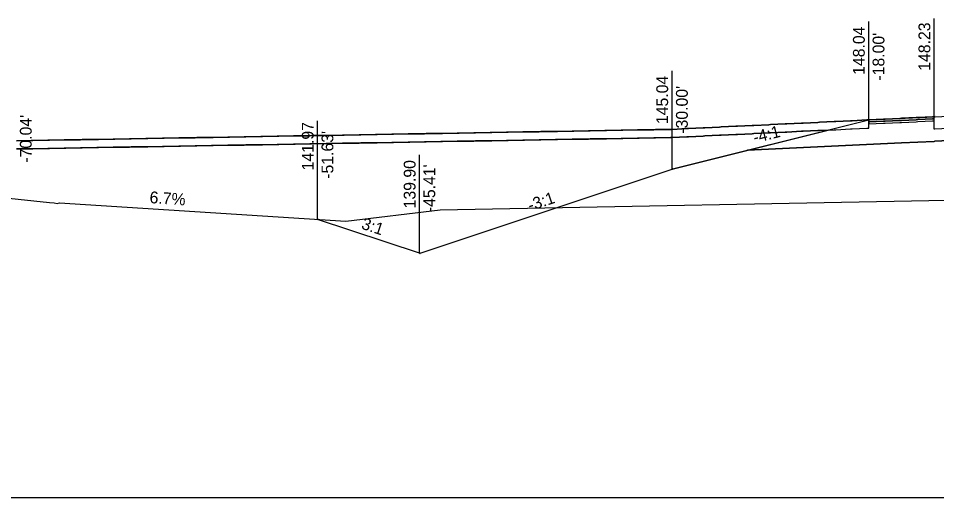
# Model space of a CAD drawing. Extents: x -26 to 4403, y -13 to 9578.
# Drawn here: x 1180.1 to 1236.1, y 1000 to 1029.2 of the extents above; entities that cross this region are included whole.
import ezdxf

# ---------------------------------------------------------------- set-up
doc = ezdxf.new("R2010")
doc.units = 0
for name, color, linetype in [('_CIVIL_CONSTRUCTION', 7, 'Continuous'), ('CONST_DCH', 7, 'Continuous'), ('CONST_LV3', 7, 'Continuous'), ('DTM_CORRIDOR', 7, 'Continuous'), ('DTM_P_FINISHED_GRADE', 7, 'Continuous'), ('DTM_TEMP_DROP', 7, 'Continuous'), ('DTM_X_GROUND', 7, 'Continuous'), ('SLOPE_STAKES_FILL', 7, 'Continuous'), ('XS_CELL', 7, 'Continuous'), ('XS_M_SHAPES_EARTHWORK', 7, 'Continuous'), ('XS_P_ASPHALT', 7, 'Continuous'), ('XS_P_DR_ASPHALT', 7, 'Continuous'), ('XS_P_DR_ASPHALT_B', 7, 'Continuous'), ('XS_P_DR_GRAVEL', 7, 'Continuous'), ('XS_P_GROUND', 7, 'Continuous'), ('XS_P_SHOULDER', 7, 'Continuous'), ('XS_P_SUBGRADE_GRANULAR', 7, 'Continuous'), ('XS_P_TX_CLEARZONE', 7, 'Continuous'), ('XS_P_TX_FS_BS', 7, 'Continuous')]:
    doc.layers.add(name, color=color, linetype=linetype)

msp = doc.modelspace()

# ---------------------------------------------------------------- linework, layer by layer
at = {"layer": 'CONST_LV3'}
for points in [[(1180, 1021.763), (1180.897, 1021.779), (1181, 1021.781), (1181.897, 1021.796), (1182, 1021.798), (1182.897, 1021.814), (1183, 1021.816), (1183.897, 1021.831), (1184, 1021.833), (1184.897, 1021.849), (1185, 1021.851), (1185.897, 1021.866), (1186, 1021.868), (1186.897, 1021.884), (1187, 1021.885), (1187.897, 1021.901), (1188, 1021.903), (1188.897, 1021.918), (1189, 1021.92), (1189.897, 1021.936), (1190, 1021.938), (1190.897, 1021.953), (1191, 1021.955), (1191.897, 1021.971), (1192, 1021.973), (1192.897, 1021.988), (1193, 1021.99), (1193.897, 1022.006), (1194, 1022.007), (1194.897, 1022.023), (1195, 1022.025), (1195.897, 1022.041), (1196, 1022.042), (1196.897, 1022.058), (1197, 1022.06), (1197.897, 1022.075), (1198, 1022.077), (1198.897, 1022.093), (1199, 1022.095), (1199.897, 1022.11), (1200, 1022.112), (1200.897, 1022.128), (1201, 1022.129), (1201.897, 1022.145), (1202, 1022.147), (1202.897, 1022.163), (1203, 1022.164), (1203.897, 1022.18), (1204, 1022.182), (1204.897, 1022.197), (1205, 1022.199), (1205.897, 1022.215), (1206, 1022.217), (1206.897, 1022.232), (1207, 1022.234), (1207.897, 1022.25), (1208, 1022.252), (1208.897, 1022.267), (1209, 1022.269), (1209.897, 1022.285), (1210, 1022.286), (1210.897, 1022.302), (1211, 1022.304), (1211.897, 1022.319), (1212, 1022.321), (1212.897, 1022.337), (1213, 1022.339), (1213.897, 1022.354), (1214, 1022.356), (1214.897, 1022.372), (1215, 1022.374), (1215.897, 1022.389), (1216, 1022.391), (1216.897, 1022.407), (1217, 1022.408), (1217.897, 1022.424), (1218, 1022.426), (1218.897, 1022.441), (1219, 1022.443), (1219.897, 1022.459), (1220, 1022.461), (1220.897, 1022.504), (1221, 1022.509), (1221.897, 1022.552), (1222, 1022.557), (1222.897, 1022.6), (1223, 1022.605), (1223.897, 1022.648), (1224, 1022.653), (1224.897, 1022.696), (1225, 1022.701), (1225.897, 1022.744), (1226, 1022.749), (1226.897, 1022.792), (1227, 1022.797), (1227.897, 1022.84), (1228, 1022.845), (1228.897, 1022.888), (1229, 1022.893), (1229.897, 1022.936), (1230, 1022.941), (1230.897, 1022.984), (1231, 1022.989), (1231.897, 1023.032), (1232, 1023.037), (1232.897, 1023.08), (1233, 1023.085), (1233.897, 1023.128), (1234, 1023.133), (1234.897, 1023.176), (1235, 1023.181), (1235.897, 1023.224), (1236, 1023.229)], [(1220, 1020.037), (1220.013, 1020.04), (1224.574, 1021.18)]]:
    msp.add_lwpolyline(points, dxfattribs=at)
at = {"layer": 'DTM_P_FINISHED_GRADE'}
for points in [[(1180, 1021.763), (1180.897, 1021.779), (1181, 1021.781), (1181.897, 1021.796), (1182, 1021.798), (1182.897, 1021.814), (1183, 1021.816), (1183.897, 1021.831), (1184, 1021.833), (1184.897, 1021.849), (1185, 1021.851), (1185.897, 1021.866), (1186, 1021.868), (1186.897, 1021.884), (1187, 1021.885), (1187.897, 1021.901), (1188, 1021.903), (1188.897, 1021.918), (1189, 1021.92), (1189.897, 1021.936), (1190, 1021.938), (1190.897, 1021.953), (1191, 1021.955), (1191.897, 1021.971), (1192, 1021.973), (1192.897, 1021.988), (1193, 1021.99), (1193.897, 1022.006), (1194, 1022.007), (1194.897, 1022.023), (1195, 1022.025), (1195.897, 1022.041), (1196, 1022.042), (1196.897, 1022.058), (1197, 1022.06), (1197.897, 1022.075), (1198, 1022.077), (1198.897, 1022.093), (1199, 1022.095), (1199.897, 1022.11), (1200, 1022.112), (1200.897, 1022.128), (1201, 1022.129), (1201.897, 1022.145), (1202, 1022.147), (1202.897, 1022.163), (1203, 1022.164), (1203.897, 1022.18), (1204, 1022.182), (1204.897, 1022.197), (1205, 1022.199), (1205.897, 1022.215), (1206, 1022.217), (1206.897, 1022.232), (1207, 1022.234), (1207.897, 1022.25), (1208, 1022.252), (1208.897, 1022.267), (1209, 1022.269), (1209.897, 1022.285), (1210, 1022.286), (1210.897, 1022.302), (1211, 1022.304), (1211.897, 1022.319), (1212, 1022.321), (1212.897, 1022.337), (1213, 1022.339), (1213.897, 1022.354), (1214, 1022.356), (1214.897, 1022.372), (1215, 1022.374), (1215.897, 1022.389), (1216, 1022.391), (1216.897, 1022.407), (1217, 1022.408), (1217.897, 1022.424), (1218, 1022.426), (1218.897, 1022.441), (1219, 1022.443), (1219.897, 1022.459), (1220, 1022.461), (1220.897, 1022.504), (1221, 1022.509), (1221.897, 1022.552), (1222, 1022.557), (1222.897, 1022.6), (1223, 1022.605), (1223.897, 1022.648), (1224, 1022.653), (1224.897, 1022.696), (1225, 1022.701), (1225.897, 1022.744), (1226, 1022.749), (1226.897, 1022.792), (1227, 1022.797), (1227.897, 1022.84), (1228, 1022.845), (1228.897, 1022.888), (1229, 1022.893), (1229.897, 1022.936), (1230, 1022.941), (1230.897, 1022.984), (1231, 1022.989), (1231.897, 1023.032), (1232, 1023.037)], [(1232, 1023.037), (1232.897, 1023.08), (1233, 1023.085), (1233.897, 1023.128), (1234, 1023.133), (1234.897, 1023.176), (1235, 1023.181), (1235.897, 1023.224), (1236, 1023.229)]]:
    msp.add_lwpolyline(points, dxfattribs=at)
at = {"layer": 'DTM_X_GROUND'}
msp.add_lwpolyline([(1084.364, 1020.049), (1100.532, 1021.44), (1114.605, 1024.089), (1116.924, 1024.52), (1120.223, 1025.074), (1123.578, 1025.386), (1123.824, 1025.384), (1125.939, 1025.479), (1126.01, 1025.486), (1135.182, 1025.868), (1142.445, 1025.917), (1146.83, 1025.95), (1147.343, 1025.854), (1148.21, 1025.742), (1149.366, 1025.63), (1164.218, 1020.156), (1164.971, 1019.814), (1182.014, 1017.995), (1182.294, 1017.975), (1182.479, 1017.946), (1182.623, 1017.982), (1200.1, 1016.861), (1205.856, 1017.542), (1237.811, 1018.169)], dxfattribs=at)
at = {"layer": 'XS_CELL'}
msp.add_line((1000, 1000), (1250, 1000), dxfattribs=at)
at = {"layer": 'XS_M_SHAPES_EARTHWORK'}
for points in [[(1250, 1022.401), (1236.039, 1021.731), (1236, 1021.729), (1234.006, 1021.633), (1234, 1021.633), (1224.601, 1021.182), (1224.574, 1021.18), (1229.525, 1022.418), (1229, 1022.393), (1228.897, 1022.388), (1228, 1022.345), (1227.897, 1022.34), (1227, 1022.297), (1226.897, 1022.292), (1226, 1022.249), (1225.897, 1022.244), (1225, 1022.201), (1224.897, 1022.196), (1224, 1022.153), (1223.897, 1022.148), (1223, 1022.105), (1222.897, 1022.1), (1222, 1022.057), (1221.897, 1022.052), (1221, 1022.009), (1220.897, 1022.004), (1220, 1021.961), (1219.897, 1021.959), (1219, 1021.943), (1218.897, 1021.941), (1218, 1021.926), (1217.897, 1021.924), (1217, 1021.908), (1216.897, 1021.907), (1216, 1021.891), (1215.897, 1021.889), (1215, 1021.874), (1214.897, 1021.872), (1214, 1021.856), (1213.897, 1021.854), (1213, 1021.839), (1212.897, 1021.837), (1212, 1021.821), (1211.897, 1021.819), (1211, 1021.804), (1210.897, 1021.802), (1210, 1021.786), (1209.897, 1021.785), (1209, 1021.769), (1208.897, 1021.767), (1208, 1021.752), (1207.897, 1021.75), (1207, 1021.734), (1206.897, 1021.732), (1206, 1021.717), (1205.897, 1021.715), (1205, 1021.699), (1204.897, 1021.697), (1204, 1021.682), (1203.897, 1021.68), (1203, 1021.664), (1202.897, 1021.663), (1202, 1021.647), (1201.897, 1021.645), (1201, 1021.629), (1200.897, 1021.628), (1200, 1021.612), (1199.897, 1021.61), (1199, 1021.595), (1198.897, 1021.593), (1198, 1021.577), (1197.897, 1021.575), (1197, 1021.56), (1196.897, 1021.558), (1196, 1021.542), (1195.897, 1021.541), (1195, 1021.525), (1194.897, 1021.523), (1194, 1021.507), (1193.897, 1021.506), (1193, 1021.49), (1192.897, 1021.488), (1192, 1021.473), (1191.897, 1021.471), (1191, 1021.455), (1190.897, 1021.453), (1190, 1021.438), (1189.897, 1021.436), (1189, 1021.42), (1188.897, 1021.418), (1188, 1021.403), (1187.897, 1021.401), (1187, 1021.385), (1186.897, 1021.384), (1186, 1021.368), (1185.897, 1021.366), (1185, 1021.351), (1184.897, 1021.349), (1184, 1021.333), (1183.897, 1021.331), (1183, 1021.316), (1182.897, 1021.314), (1182, 1021.298), (1181.897, 1021.296), (1181, 1021.281), (1180.897, 1021.279), (1180, 1021.263)], [(1164.971, 1019.814), (1182.014, 1017.995), (1182.294, 1017.975), (1182.479, 1017.946), (1182.623, 1017.982), (1200.1, 1016.861), (1205.856, 1017.542), (1237.811, 1018.169)]]:
    msp.add_lwpolyline(points, dxfattribs=at)
at = {"layer": 'XS_P_ASPHALT'}
msp.add_lwpolyline([(1236.039, 1023.231), (1250, 1023.901), (1250.039, 1023.903), (1264, 1024.573), (1264, 1023.825), (1264, 1023.823), (1250.039, 1023.153), (1250, 1023.151), (1236.039, 1022.481), (1236, 1022.479), (1236, 1022.481), (1236, 1023.229), (1236.039, 1023.231)], dxfattribs=at)
at = {"layer": 'XS_P_DR_ASPHALT'}
msp.add_lwpolyline([(1232, 1023.037), (1232, 1022.912), (1232.897, 1022.955), (1232.897, 1022.955), (1233, 1022.96), (1233.897, 1023.003), (1233.897, 1023.003), (1234, 1023.008), (1234.897, 1023.051), (1235, 1023.056), (1235, 1023.056), (1235.897, 1023.099), (1236, 1023.104), (1236, 1023.229), (1235.897, 1023.224), (1235, 1023.181), (1235, 1023.181), (1234.897, 1023.176), (1234, 1023.133), (1233.897, 1023.128), (1233.897, 1023.128), (1233, 1023.085), (1232.897, 1023.08), (1232.897, 1023.08), (1232, 1023.037)], dxfattribs=at)
at = {"layer": 'XS_P_DR_ASPHALT_B'}
msp.add_lwpolyline([(1232, 1022.912), (1232, 1022.787), (1232.897, 1022.83), (1232.897, 1022.83), (1233, 1022.835), (1233.897, 1022.878), (1233.897, 1022.878), (1234, 1022.883), (1234.897, 1022.926), (1235, 1022.931), (1235, 1022.931), (1235.897, 1022.974), (1236, 1022.979), (1236, 1023.104), (1235.897, 1023.099), (1235, 1023.056), (1235, 1023.056), (1234.897, 1023.051), (1234, 1023.008), (1233.897, 1023.003), (1233.897, 1023.003), (1233, 1022.96), (1232.897, 1022.955), (1232.897, 1022.955), (1232, 1022.912)], dxfattribs=at)
at = {"layer": 'XS_P_DR_GRAVEL'}
msp.add_lwpolyline([(1180, 1021.263), (1180.897, 1021.279), (1181, 1021.281), (1181.897, 1021.296), (1182, 1021.298), (1182.897, 1021.314), (1183, 1021.316), (1183.897, 1021.331), (1184, 1021.333), (1184.897, 1021.349), (1185, 1021.351), (1185.897, 1021.366), (1186, 1021.368), (1186.897, 1021.384), (1187, 1021.385), (1187.897, 1021.401), (1188, 1021.403), (1188.897, 1021.418), (1189, 1021.42), (1189.897, 1021.436), (1190, 1021.438), (1190.897, 1021.453), (1191, 1021.455), (1191.897, 1021.471), (1192, 1021.473), (1192.897, 1021.488), (1193, 1021.49), (1193.897, 1021.506), (1194, 1021.507), (1194.897, 1021.523), (1195, 1021.525), (1195.897, 1021.541), (1196, 1021.542), (1196.897, 1021.558), (1197, 1021.56), (1197.897, 1021.575), (1198, 1021.577), (1198.897, 1021.593), (1199, 1021.595), (1199.897, 1021.61), (1200, 1021.612), (1200.897, 1021.628), (1201, 1021.629), (1201.897, 1021.645), (1202, 1021.647), (1202.897, 1021.663), (1203, 1021.664), (1203.897, 1021.68), (1204, 1021.682), (1204.897, 1021.697), (1205, 1021.699), (1205.897, 1021.715), (1206, 1021.717), (1206.897, 1021.732), (1207, 1021.734), (1207.897, 1021.75), (1208, 1021.752), (1208.897, 1021.767), (1209, 1021.769), (1209.897, 1021.785), (1210, 1021.786), (1210.897, 1021.802), (1211, 1021.804), (1211.897, 1021.819), (1212, 1021.821), (1212.897, 1021.837), (1213, 1021.839), (1213.897, 1021.854), (1214, 1021.856), (1214.897, 1021.872), (1215, 1021.874), (1215.897, 1021.889), (1216, 1021.891), (1216.897, 1021.907), (1217, 1021.908), (1217.897, 1021.924), (1218, 1021.926), (1218.897, 1021.941), (1219, 1021.943), (1219.897, 1021.959), (1220, 1021.961), (1220.897, 1022.004), (1221, 1022.009), (1221.897, 1022.052), (1222, 1022.057), (1222.897, 1022.1), (1223, 1022.105), (1223.897, 1022.148), (1224, 1022.153), (1224.897, 1022.196), (1225, 1022.201), (1225.897, 1022.244), (1226, 1022.249), (1226.897, 1022.292), (1227, 1022.297), (1227.897, 1022.34), (1227.897, 1022.34), (1228, 1022.345), (1228.897, 1022.388), (1229, 1022.393), (1229.897, 1022.436), (1230, 1022.441), (1230.897, 1022.484), (1231, 1022.489), (1231.897, 1022.532), (1232, 1022.537), (1232, 1023.037), (1231.897, 1023.032), (1231, 1022.989), (1230.897, 1022.984), (1230, 1022.941), (1229.897, 1022.936), (1229, 1022.893), (1228.897, 1022.888), (1228, 1022.845), (1227.897, 1022.84), (1227.897, 1022.84), (1227, 1022.797), (1226.897, 1022.792), (1226, 1022.749), (1225.897, 1022.744), (1225, 1022.701), (1224.897, 1022.696), (1224, 1022.653), (1223.897, 1022.648), (1223, 1022.605), (1222.897, 1022.6), (1222, 1022.557), (1221.897, 1022.552), (1221, 1022.509), (1220.897, 1022.504), (1220, 1022.461), (1219.897, 1022.459), (1219, 1022.443), (1218.897, 1022.441), (1218, 1022.426), (1217.897, 1022.424), (1217, 1022.408), (1216.897, 1022.407), (1216, 1022.391), (1215.897, 1022.389), (1215, 1022.374), (1214.897, 1022.372), (1214, 1022.356), (1213.897, 1022.354), (1213, 1022.339), (1212.897, 1022.337), (1212, 1022.321), (1211.897, 1022.319), (1211, 1022.304), (1210.897, 1022.302), (1210, 1022.286), (1209.897, 1022.285), (1209, 1022.269), (1208.897, 1022.267), (1208, 1022.252), (1207.897, 1022.25), (1207, 1022.234), (1206.897, 1022.232), (1206, 1022.217), (1205.897, 1022.215), (1205, 1022.199), (1204.897, 1022.197), (1204, 1022.182), (1203.897, 1022.18), (1203, 1022.164), (1202.897, 1022.163), (1202, 1022.147), (1201.897, 1022.145), (1201, 1022.129), (1200.897, 1022.128), (1200, 1022.112), (1199.897, 1022.11), (1199, 1022.095), (1198.897, 1022.093), (1198, 1022.077), (1197.897, 1022.075), (1197, 1022.06), (1196.897, 1022.058), (1196, 1022.042), (1195.897, 1022.041), (1195, 1022.025), (1194.897, 1022.023), (1194, 1022.007), (1193.897, 1022.006), (1193, 1021.99), (1192.897, 1021.988), (1192, 1021.973), (1191.897, 1021.971), (1191, 1021.955), (1190.897, 1021.953), (1190, 1021.938), (1189.897, 1021.936), (1189, 1021.92), (1188.897, 1021.918), (1188, 1021.903), (1187.897, 1021.901), (1187, 1021.885), (1186.897, 1021.884), (1186, 1021.868), (1185.897, 1021.866), (1185, 1021.851), (1184.897, 1021.849), (1184, 1021.833), (1183.897, 1021.831), (1183, 1021.816), (1182.897, 1021.814), (1182, 1021.798), (1181.897, 1021.796), (1181, 1021.781), (1180.897, 1021.779), (1180, 1021.763)], dxfattribs=at)
at = {"layer": 'XS_P_GROUND'}
for points in [[(1204.587, 1014.9), (1204.63, 1014.914), (1220, 1020.037), (1220.033, 1020.045), (1232, 1023.037)], [(1204.587, 1014.9), (1198.37, 1016.972)]]:
    msp.add_lwpolyline(points, dxfattribs=at)
at = {"layer": 'XS_P_SHOULDER'}
msp.add_lwpolyline([(1232, 1023.037), (1232.011, 1023.037), (1236, 1023.229)], dxfattribs=at)
at = {"layer": 'XS_P_SUBGRADE_GRANULAR'}
for points in [[(1236, 1021.729), (1236.039, 1021.731), (1250, 1022.401)], [(1224.574, 1021.18), (1224.601, 1021.182), (1234, 1021.633), (1234.006, 1021.633), (1236, 1021.729)]]:
    msp.add_lwpolyline(points, dxfattribs=at)
at = {"layer": 'XS_P_TX_CLEARZONE'}
for p, q in [((1232, 1023.037), (1232, 1029.037)), ((1232, 1023.037), (1232, 1029.037)), ((1232, 1023.037), (1232, 1029.037)), ((1236, 1023.229), (1236, 1029.229)), ((1236, 1023.229), (1236, 1029.229)), ((1236, 1023.229), (1236, 1029.229)), ((1236, 1023.229), (1236, 1029.229)), ((1236, 1023.229), (1236, 1029.229)), ((1236, 1023.229), (1236, 1029.229)), ((1220, 1020.037), (1220, 1026.037)), ((1220, 1020.037), (1220, 1026.037)), ((1220, 1020.037), (1220, 1026.037)), ((1198.37, 1016.972), (1198.37, 1022.972)), ((1198.37, 1016.972), (1198.37, 1022.972)), ((1198.37, 1016.972), (1198.37, 1022.972)), ((1198.37, 1016.972), (1198.37, 1022.972)), ((1198.37, 1016.972), (1198.37, 1022.972)), ((1198.37, 1016.972), (1198.37, 1022.972)), ((1204.587, 1014.9), (1204.587, 1020.9)), ((1204.587, 1014.9), (1204.587, 1020.9)), ((1204.587, 1014.9), (1204.587, 1020.9))]:
    msp.add_line(p, q, dxfattribs=at)

# ---------------------------------------------------------------- texts
at = {"layer": '_CIVIL_CONSTRUCTION'}
msp.add_text('X', height=0.12, dxfattribs=at).set_placement((1235.961, 1023.169))
at = {"layer": 'CONST_DCH'}
msp.add_text('X', height=0.12, dxfattribs=at).set_placement((1204.548, 1014.84))
at = {"layer": 'DTM_CORRIDOR'}
msp.add_text('X', height=0.12, dxfattribs=at).set_placement((1198.331, 1016.912))
at = {"layer": 'DTM_TEMP_DROP'}
msp.add_text('X', height=0.12, dxfattribs=at).set_placement((1231.961, 1022.977))
at = {"layer": 'SLOPE_STAKES_FILL'}
msp.add_text('X', height=0.12, dxfattribs=at).set_placement((1219.961, 1019.977))
at = {"layer": 'XS_P_TX_CLEARZONE'}
for s, p in [('148.23', (1235.76, 1026.033)), ('148.23', (1235.76, 1026.033)), ('148.23', (1235.76, 1026.033)), ('148.23', (1235.76, 1026.033)), ('148.23', (1235.76, 1026.033)), ('148.23', (1235.76, 1026.033)), ('148.04', (1231.76, 1025.784)), ('148.04', (1231.76, 1025.784)), ('148.04', (1231.76, 1025.784)), ("-18.00'", (1232.96, 1025.433)), ("-18.00'", (1232.96, 1025.433)), ("-18.00'", (1232.96, 1025.433)), ('145.04', (1219.76, 1022.784)), ('145.04', (1219.76, 1022.784)), ('145.04', (1219.76, 1022.784)), ("-30.00'", (1220.96, 1022.195)), ("-30.00'", (1220.96, 1022.195)), ("-30.00'", (1220.96, 1022.195)), ("-70.04'", (1180.922, 1020.429)), ("-70.04'", (1180.922, 1020.429)), ("-70.04'", (1180.922, 1020.429)), ("-70.04'", (1180.922, 1020.429)), ("-70.04'", (1180.922, 1020.429)), ("-70.04'", (1180.922, 1020.429)), ('141.97', (1198.13, 1019.958)), ('141.97', (1198.13, 1019.958)), ('141.97', (1198.13, 1019.958)), ('141.97', (1198.13, 1019.958)), ('141.97', (1198.13, 1019.958)), ('141.97', (1198.13, 1019.958)), ("-51.63'", (1199.33, 1019.447)), ("-51.63'", (1199.33, 1019.447)), ("-51.63'", (1199.33, 1019.447)), ("-51.63'", (1199.33, 1019.447)), ("-51.63'", (1199.33, 1019.447)), ("-51.63'", (1199.33, 1019.447)), ('139.90', (1204.347, 1017.641)), ('139.90', (1204.347, 1017.641)), ('139.90', (1204.347, 1017.641)), ("-45.41'", (1205.547, 1017.409)), ("-45.41'", (1205.547, 1017.409)), ("-45.41'", (1205.547, 1017.409))]:
    msp.add_text(s, height=0.72, rotation=90, dxfattribs=at).set_placement(p)
at = {"layer": 'XS_P_TX_FS_BS'}
for s, rotation, p in [('-4:1', 14.0362, (1225.047, 1021.608)), ('-4:1', 14.0362, (1225.047, 1021.608)), ('-4:1', 14.0362, (1225.047, 1021.608)), ('6.7%', 356.1386, (1188.098, 1017.966)), ('6.7%', 356.1386, (1188.098, 1017.966)), ('6.7%', 356.1386, (1188.098, 1017.966)), ('-3:1', 18.4332, (1211.338, 1017.466)), ('-3:1', 18.4332, (1211.338, 1017.466)), ('-3:1', 18.4332, (1211.338, 1017.466)), ('3:1', 341.5651, (1200.993, 1016.414)), ('3:1', 341.5651, (1200.993, 1016.414)), ('3:1', 341.5651, (1200.993, 1016.414))]:
    msp.add_text(s, height=0.72, rotation=rotation, dxfattribs=at).set_placement(p)

doc.saveas('drawing.dxf')
